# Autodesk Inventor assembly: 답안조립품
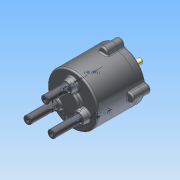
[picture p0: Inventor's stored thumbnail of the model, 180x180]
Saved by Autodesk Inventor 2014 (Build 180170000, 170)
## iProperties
Created: 2015-09
Part Number: 답안조립품
Document SubType Name: Assembly
Designer: study
Mass: 2160.25 g
Surface Area: 1801.24 cm^2
Volume: 438.523 cm^3
Density: 4.9262 g/cm^3
Author: study
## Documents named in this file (14)
- C:\Users\study\Desktop\350916V1019\답안조립품.iam
- C:\Users\study\Desktop\350916V1019\몸체.ipt
- C:\Users\study\Desktop\350916V1019\커버.ipt
- C:\Users\study\Desktop\350916V1019\오일실.ipt
- C:\Users\study\Desktop\350916V1019\M5x0.8x20.ipt
- C:\Users\study\Desktop\350916V1019\베어링 NA 4900.ipt
- C:\Users\study\Desktop\350916V1019\멈춤링 22 x 1.2.ipt
- C:\Users\study\Desktop\350916V1019\메인 축.ipt
- C:\Users\study\Desktop\350916V1019\판캠.ipt
- C:\Users\study\Desktop\350916V1019\멈춤링 10 x 1.ipt
- C:\Users\study\Desktop\350916V1019\슬라이드 축.ipt
- C:\Users\study\Desktop\350916V1019\11-가변스프링.ipt
- C:\Users\study\Desktop\350916V1019\12-가변스프링.ipt
- C:\Users\study\Desktop\350916V1019\13-가변스프링.ipt
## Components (7 placed, 4 different names)
1. 11-가변스프링:1
2. 12-가변스프링:1
3. 13-가변스프링:1
4. M5x0.8x20:1
5. M5x0.8x20:2
6. M5x0.8x20:3
7. M5x0.8x20:4
